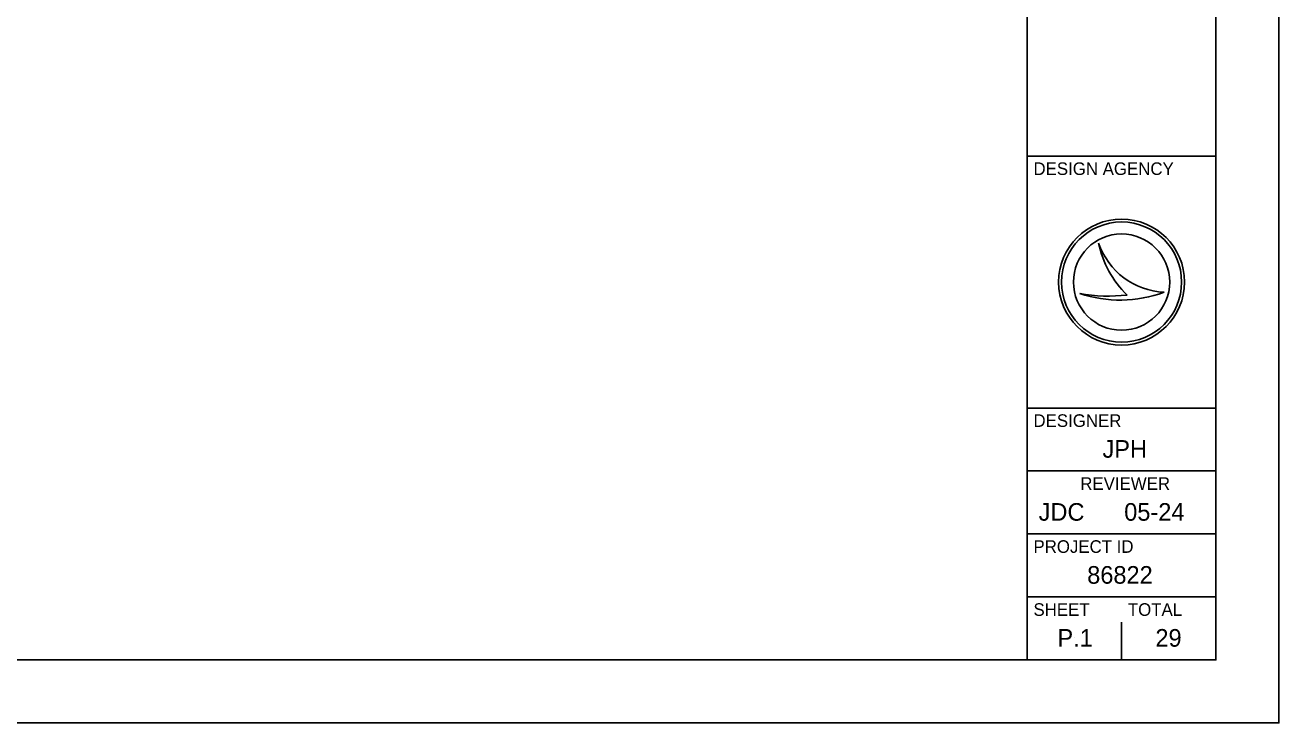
# Model space of a CAD drawing. Extents: x 21.4 to 65.3, y 4 to 26.
# Drawn here: x 45.49 to 55.45, y 3.95 to 9.49 of the extents above; entities that cross this region are included whole.
import ezdxf

# ---------------------------------------------------------------- set-up
doc = ezdxf.new("R2010")
doc.units = 0
for name, color, linetype in [('SH_Border', 7, 'Continuous'), ('SH_Cut_Line', 7, 'Continuous'), ('SH_Data', 7, 'Continuous')]:
    doc.layers.add(name, color=color, linetype=linetype)

msp = doc.modelspace()

# ---------------------------------------------------------------- linework, layer by layer
at = {"layer": 'SH_Border'}
for p, q in [((53.4473, 4.4542), (53.4473, 25.4542)), ((53.4473, 8.4542), (54.9473, 8.4542)), ((53.4473, 6.4542), (54.9473, 6.4542)), ((53.4473, 5.9542), (54.9473, 5.9542)), ((53.4473, 5.4542), (54.9473, 5.4542)), ((53.4473, 4.9542), (54.9473, 4.9542))]:
    msp.add_line(p, q, dxfattribs=at)
msp.add_lwpolyline([(22.9473, 25.4542), (54.9473, 25.4542), (54.9473, 4.4542), (22.9473, 4.4542)], close=True, dxfattribs=at)
at = {"layer": 'SH_Cut_Line'}
msp.add_lwpolyline([(21.4473, 3.9542), (55.4473, 3.9542), (55.4473, 25.9542), (21.4473, 25.9542)], close=True, dxfattribs=at)
at = {"layer": 'SH_Data'}
for p, q in [((54.0148, 7.7637), (54.0148, 7.7637)), ((54.1973, 7.4542), (54.1973, 7.4542)), ((54.5346, 7.3727), (54.5346, 7.3727)), ((53.8645, 7.3637), (53.8645, 7.3637)), ((54.1973, 4.4542), (54.1973, 4.7542)), ((53.8223, 4.6292), (53.8223, 4.6292))]:
    msp.add_line(p, q, dxfattribs=at)
for radius in [0.5, 0.4768, 0.4768, 0.3822]:
    msp.add_circle((54.1973, 7.4542), radius, dxfattribs=at)
for centre, radius, start, end in [((54.5633, 7.9518), 0.5798, 198.92567, 198.93195), ((54.794, 7.9242), 0.7956, 191.63793, 191.64215), ((54.5633, 7.9518), 0.5798, 198.93195, 267.16574), ((54.794, 7.9242), 0.7956, 191.64215, 226.09467), ((54.1867, 8.3242), 1.0131, 251.45764, 290.08324), ((54.0953, 8.6085), 1.2661, 259.49639, 259.49952), ((54.1867, 8.3242), 1.0131, 251.45274, 251.45764), ((54.0953, 8.6085), 1.2661, 259.49952, 276.66723)]:
    msp.add_arc(centre, radius, start, end, dxfattribs=at)

# ---------------------------------------------------------------- texts
for s, height, p in [('DESIGN AGENCY', 0.1, (53.4973, 8.3042)), ('DESIGNER', 0.1, (53.4973, 6.3042)), ('JPH', 0.14, (54.0457, 6.0592)), ('REVIEWER', 0.1, (53.8692, 5.8042)), ('JDC', 0.14, (53.5385, 5.5592)), ('05-24', 0.14, (54.2182, 5.5592)), ('PROJECT ID', 0.1, (53.4973, 5.3042)), ('86822', 0.14, (53.9241, 5.0592)), ('SHEET', 0.1, (53.4973, 4.8042)), ('TOTAL', 0.1, (54.2473, 4.8042)), ('P.1', 0.14, (53.6876, 4.5592)), ('29', 0.14, (54.4662, 4.5592))]:
    msp.add_text(s, height=height, dxfattribs=at).set_placement(p)

doc.saveas('drawing.dxf')
